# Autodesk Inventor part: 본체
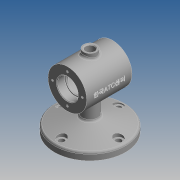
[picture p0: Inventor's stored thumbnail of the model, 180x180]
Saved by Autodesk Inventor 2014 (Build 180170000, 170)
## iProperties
Created: 2018-12
Part Number: 본체
Material: 일반
Document SubType Name: Modeling
Designer: 601-25
Density: 1 g/cm^3
Appearance: 기본값
Mass: 252.797 g
Surface Area: 555.531 cm^2
Volume: 252.797 cm^3
Author: 601-25
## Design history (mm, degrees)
sketch "스케치2"
  geometry: L1 (-35, 0)-(35, 0); L2 (-35, 30)-(35, 30); L3 (-35, 30)-(-35, 16); L4 (-35, 16)-(-23, 16); L5 (-23, 16)-(-23, 14); L6 (-23, 14)-(-20, 14); L7 (-20, 14)-(-20, 25); L8 (-20, 25)-(20, 25); L9 (20, 25)-(20, 14); L10 (20, 14)-(23, 14); L11 (23, 14)-(23, 16); L12 (23, 16)-(35, 16); L13 (35, 16)-(35, 30); 2 further points
  constraints: 26 end point, 6 perpendicular, 5 parallel, 4 collinear, 2 horizontal, 2 vertical alignment, 1 coincident, 1 midpoint
  dimensions: "d0" = 70 distance of L1.start L1.end; "d1" = 60 diameter of L2 L1; "d2" = 32 diameter of L12 L1; "d3" = 28 diameter of L10 L1; "d4" = 50 diameter of L8 L1; "d5" = 12 distance of L3.end L4.end; "d6" = 3 distance of L5.end L6.end
revolve "회전1" sketch "스케치2" stored, may be unused: angle "d7" = 90 deg
chamfer "모따기1" distance "d8" = 1; stored, may be unused: second distance "d9" = 2, angle "d10" = 45 deg
sketch "스케치3"
  geometry: L1 (0, -75)-(-55, -75); L2 (-55, -75)-(-55, -64); L3 (-55, -64)-(0, -49.263); L4 (0, -49.263)-(0, -75); 1 further point
  constraints: 8 end point, 1 horizontal, 1 parallel, 1 perpendicular, 1 vertical alignment
  dimensions: "d11" = 11 distance of L1.end L2.end; "d12" = 55 distance between parallel lines of L2 L4; "d13" = 75 distance from line of L1 point (0, 0); "d14" = 75 deg angle of L3 L2
revolve "회전2" sketch "스케치3" stored, may be unused: angle "d15" = 90 deg
sketch "스케치4"
  geometry: C1 r 55 at (0, 0) reference; C2 r 12 at (0, 0)
  constraints: 1 centre point, 1 coincident
  dimensions: "d16" = 24 diameter of C2
extrude "돌출1" join sketch "스케치4" stored distance "d17" = 10; taper "d18" = 0 deg
fillet "모깎기1" dims "d19" = 0.3, "d20" = 3
sketch "스케치5"
  geometry: C1 r 55 at (0, 0) reference; 1 further point
  constraints: 1 vertical alignment
  dimensions: "d21" = 44 distance of C1.centre point (0, 44)
hole "구멍1" sketch "스케치5" at (0, 44) diameter "d22" = 9; stored, may be unused: countersink angle "d26" = 90 deg, drill point angle "d28" = 0 deg; dims "d23" = 6, "d24" = 4, "d25" = 2, "d27" = 10
hole "구멍2" diameter "d31" = 14; stored, may be unused: countersink angle "d35" = 90 deg, drill point angle "d37" = 0 deg; dims "d29" = 10, "d30" = 10, "d32" = 6, "d33" = 4, "d34" = 2, "d36" = 10
fillet "모깎기2" dims "d41" = 3
sketch "스케치6"
  geometry: C1 r 30 at (0, 0) reference; 1 further point
  constraints: 1 vertical alignment
  dimensions: "d42" = 23 distance of C1.centre point (0, 23)
hole "구멍3" sketch "스케치6" at (0, 23) diameter "d43" = 3.242; stored, may be unused: countersink angle "d47" = 90 deg, drill point angle "d49" = 118 deg; dims "d44" = 8, "d45" = 4, "d46" = 2, "d48" = 10
node "작업 평면1"
sketch "스케치7"
  geometry: C1 r 10 at (0, 0); 1 further point
  constraints: 1 centre point, 1 coincident
  dimensions: "d54" = 20 diameter of C1
extrude "돌출2" join sketch "스케치7" stored distance "d55" = 10; taper "d56" = 0 deg
hole "구멍4" diameter "d59" = 14; stored, may be unused: countersink angle "d63" = 90 deg, drill point angle "d65" = 0 deg; dims "d57" = 10, "d58" = 10, "d60" = 10, "d61" = 4, "d62" = 2, "d64" = 10
chamfer "모따기2" distance "d66" = 1; stored, may be unused: second distance "d67" = 2, angle "d68" = 45 deg
fillet "모깎기3" dims "d69" = 3
node "작업 평면2"
sketch "스케치8"
  geometry: L1 (-35, -30)-(-35, 30) reference; 2 further points
  constraints: 1 other
  dimensions: "d70" = 35 distance from line of point (0, 0) L1; "d71" = 30 vertical distance of L1.end point (0, 0)
feature "엠보싱1" sketch "스케치8" dims "d0" = 70, "d1" = 60, "d2" = 32, "d3" = 28, "d4" = 50, "d5" = 12, "d6" = 3, "d11" = 11, "d12" = 55, "d13" = 75, "d14" = 75 deg, "d72" = 0.5, "d73" = 0
node "솔리드1"
pattern_circular "원형 패턴1" dims angle "d39" = 360 deg
pattern_circular "원형 패턴2" dims angle "d51" = 360 deg
mirror "대칭1"
other parameters: "d53" = 37
